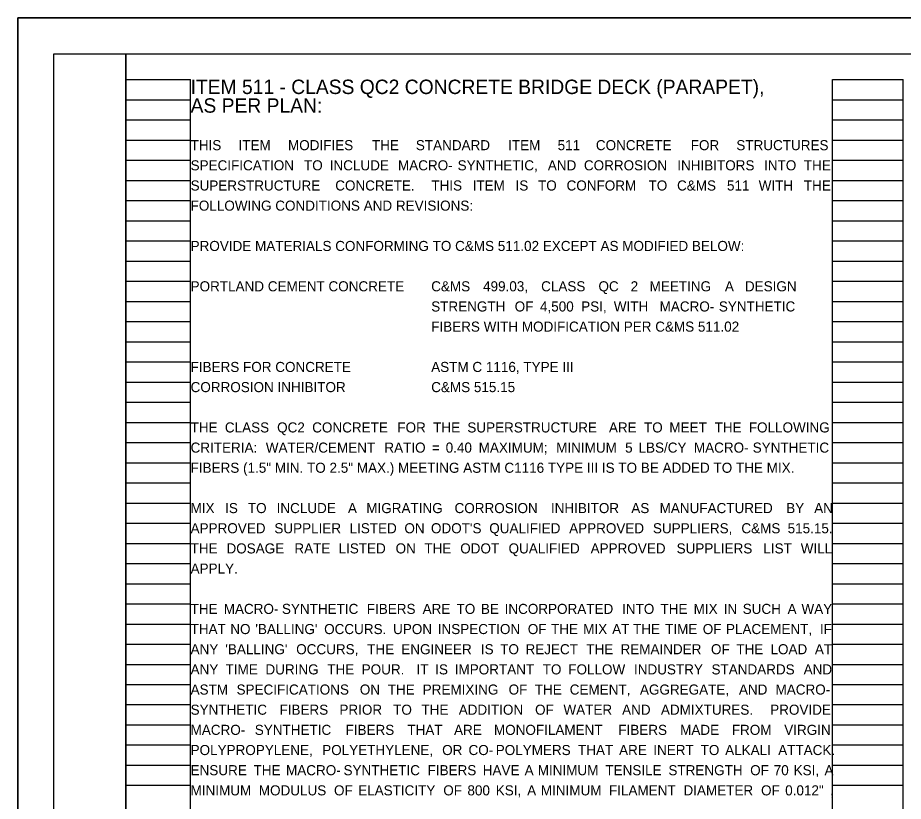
# Model space of a CAD drawing. Extents: x 0 to 34, y 0 to 22.
# Drawn here: x 0 to 12.29, y 11.12 to 22 of the extents above; entities that cross this region are included whole.
import ezdxf

# ---------------------------------------------------------------- set-up
doc = ezdxf.new("R2010")
doc.units = 0
for name, color, linetype in [('BR_P_Gen_Text', 7, 'Continuous'), ('SC_Scratch1', 7, 'Continuous'), ('SH_Border', 7, 'Continuous'), ('SH_Cut_Line', 7, 'Continuous'), ('SH_Text', 7, 'Continuous'), ('SN_P_Cantilever_Overhead', 7, 'Continuous')]:
    doc.layers.add(name, color=color, linetype=linetype)

msp = doc.modelspace()

# ---------------------------------------------------------------- linework, layer by layer
at = {"layer": 'SC_Scratch1'}
for p, q in [((1.5, 0.98), (1.5, 21.14)), ((1.5, 21.14), (2.4, 21.14)), ((2.4, 0.98), (2.4, 21.14)), ((11.313, 0.98), (11.313, 21.14)), ((11.313, 21.14), (12.293, 21.14)), ((12.293, 0.98), (12.293, 21.14)), ((1.5, 20.86), (2.4, 20.86)), ((11.313, 20.86), (12.293, 20.86)), ((1.5, 20.58), (2.4, 20.58)), ((11.313, 20.58), (12.293, 20.58)), ((1.5, 20.3), (2.4, 20.3)), ((11.313, 20.3), (12.293, 20.3)), ((1.5, 20.02), (2.4, 20.02)), ((11.313, 20.02), (12.293, 20.02)), ((1.5, 19.74), (2.4, 19.74)), ((11.313, 19.74), (12.293, 19.74)), ((1.5, 19.46), (2.4, 19.46)), ((11.313, 19.46), (12.293, 19.46)), ((1.5, 19.18), (2.4, 19.18)), ((11.313, 19.18), (12.293, 19.18)), ((1.5, 18.9), (2.4, 18.9)), ((11.313, 18.9), (12.293, 18.9)), ((1.5, 18.62), (2.4, 18.62)), ((11.313, 18.62), (12.293, 18.62)), ((1.5, 18.34), (2.4, 18.34)), ((11.313, 18.34), (12.293, 18.34)), ((1.5, 18.06), (2.4, 18.06)), ((11.313, 18.06), (12.293, 18.06)), ((1.5, 17.78), (2.4, 17.78)), ((11.313, 17.78), (12.293, 17.78)), ((1.5, 17.5), (2.4, 17.5)), ((11.313, 17.5), (12.293, 17.5)), ((1.5, 17.22), (2.4, 17.22)), ((11.313, 17.22), (12.293, 17.22)), ((1.5, 16.94), (2.4, 16.94)), ((11.313, 16.94), (12.293, 16.94)), ((1.5, 16.66), (2.4, 16.66)), ((11.313, 16.66), (12.293, 16.66)), ((1.5, 16.38), (2.4, 16.38)), ((11.313, 16.38), (12.293, 16.38)), ((1.5, 16.1), (2.4, 16.1)), ((11.313, 16.1), (12.293, 16.1)), ((1.5, 15.82), (2.4, 15.82)), ((11.313, 15.82), (12.293, 15.82)), ((1.5, 15.54), (2.4, 15.54)), ((11.313, 15.54), (12.293, 15.54)), ((1.5, 15.26), (2.4, 15.26)), ((11.313, 15.26), (12.293, 15.26)), ((1.5, 14.98), (2.4, 14.98)), ((11.313, 14.98), (12.293, 14.98)), ((1.5, 14.7), (2.4, 14.7)), ((11.313, 14.7), (12.293, 14.7)), ((1.5, 14.42), (2.4, 14.42)), ((11.313, 14.42), (12.293, 14.42)), ((1.5, 14.14), (2.4, 14.14)), ((11.313, 14.14), (12.293, 14.14)), ((1.5, 13.86), (2.4, 13.86)), ((11.313, 13.86), (12.293, 13.86)), ((1.5, 13.58), (2.4, 13.58)), ((11.313, 13.58), (12.293, 13.58)), ((1.5, 13.3), (2.4, 13.3)), ((11.313, 13.3), (12.293, 13.3)), ((1.5, 13.02), (2.4, 13.02)), ((11.313, 13.02), (12.293, 13.02)), ((1.5, 12.74), (2.4, 12.74)), ((11.313, 12.74), (12.293, 12.74)), ((1.5, 12.46), (2.4, 12.46)), ((11.313, 12.46), (12.293, 12.46)), ((1.5, 12.18), (2.4, 12.18)), ((11.313, 12.18), (12.293, 12.18)), ((1.5, 11.9), (2.4, 11.9)), ((11.313, 11.9), (12.293, 11.9)), ((1.5, 11.62), (2.4, 11.62)), ((11.313, 11.62), (12.293, 11.62)), ((1.5, 11.34), (2.4, 11.34)), ((11.313, 11.34), (12.293, 11.34))]:
    msp.add_line(p, q, dxfattribs=at)
msp.add_lwpolyline([(0, 22), (34, 22), (34, 0), (0, 0)], close=True, dxfattribs=at)
at = {"layer": 'SH_Border'}
for points in [[(0.5, 21.5), (1.5, 21.5), (1.5, 0.5), (0.5, 0.5)], [(1.5, 21.5), (33.5, 21.5), (33.5, 0.5), (1.5, 0.5)]]:
    msp.add_lwpolyline(points, close=True, dxfattribs=at)
at = {"layer": 'SH_Cut_Line'}
msp.add_lwpolyline([(0, 0), (34, 0), (34, 22), (0, 22)], close=True, dxfattribs=at)

# ---------------------------------------------------------------- texts
at = {"layer": 'BR_P_Gen_Text'}
for s, p in [('ITEM 511 - CLASS QC2 CONCRETE BRIDGE DECK (PARAPET), ', (2.4, 20.94)), ('AS PER PLAN:', (2.4, 20.681))]:
    msp.add_text(s, height=0.2, dxfattribs=at).set_placement(p)
at = {"layer": 'SH_Text'}
for s, p in [('THIS ', (2.4, 20.16)), ('ITEM ', (3.065, 20.16)), ('MODIFIES ', (3.752, 20.16)), ('THE ', (4.917, 20.16)), ('STANDARD ', (5.527, 20.16)), ('ITEM ', (6.808, 20.16)), ('511 ', (7.495, 20.16)), ('CONCRETE ', (8.026, 20.16)), ('FOR ', (9.343, 20.16)), ('STRUCTURES ', (9.976, 20.16)), ('SPECIFICATION ', (2.4, 19.88)), ('TO ', (3.974, 19.88)), ('INCLUDE ', (4.331, 19.88)), ('MACRO-', (5.279, 19.88)), ('SYNTHETIC, ', (6.107, 19.88)), ('AND ', (7.359, 19.88)), ('CORROSION ', (7.86, 19.88)), ('INHIBITORS ', (9.156, 19.88)), ('INTO ', (10.361, 19.88)), ('THE ', (10.913, 19.88)), ('SUPERSTRUCTURE ', (2.4, 19.6)), ('CONCRETE.  ', (4.408, 19.6)), ('THIS ', (5.742, 19.6)), ('ITEM ', (6.316, 19.6)), ('IS ', (6.911, 19.6)), ('TO ', (7.223, 19.6)), ('CONFORM ', (7.619, 19.6)), ('TO ', (8.757, 19.6)), ('C&MS ', (9.153, 19.6)), ('511 ', (9.846, 19.6)), ('WITH ', (10.286, 19.6)), ('THE ', (10.913, 19.6)), ('FOLLOWING CONDITIONS AND REVISIONS:', (2.4, 19.32)), ('PROVIDE MATERIALS CONFORMING TO C&MS 511.02 EXCEPT AS MODIFIED BELOW:', (2.4, 18.76)), ('PORTLAND CEMENT CONCRETE', (2.4, 18.2)), ('FIBERS FOR CONCRETE', (2.4, 17.08)), ('CORROSION INHIBITOR', (2.4, 16.8)), ('THE ', (2.4, 16.24)), ('CLASS ', (2.876, 16.24)), ('QC2 ', (3.601, 16.24)), ('CONCRETE ', (4.088, 16.24)), ('FOR ', (5.27, 16.24)), ('THE ', (5.767, 16.24)), ('SUPERSTRUCTURE ', (6.242, 16.24)), ('ARE ', (8.207, 16.24)), ('TO ', (8.694, 16.24)), ('MEET ', (9.046, 16.24)), ('THE ', (9.674, 16.24)), ('FOLLOWING ', (10.149, 16.24)), ('WATER/CEMENT ', (3.444, 15.96)), ('LBS/CY ', (8.618, 15.96)), ('CRITERIA: ', (2.4, 15.96)), ('RATIO ', (5.09, 15.96)), ('= ', (5.75, 15.96)), ('0.40 ', (5.941, 15.96)), ('MAXIMUM; ', (6.399, 15.96)), ('MINIMUM ', (7.475, 15.96)), ('5 ', (8.432, 15.96)), ('MACRO-', (9.387, 15.96)), ('SYNTHETIC ', (10.203, 15.96)), ('FIBERS (1.5" MIN. TO 2.5" MAX.) MEETING ASTM C1116 TYPE III IS TO BE ADDED TO THE MIX.', (2.4, 15.68)), ('MIX ', (2.4, 15.12)), ('IS ', (2.879, 15.12)), ('TO ', (3.195, 15.12)), ('INCLUDE ', (3.594, 15.12)), ('A ', (4.584, 15.12)), ('MIGRATING ', (4.839, 15.12)), ('CORROSION ', (6.064, 15.12)), ('INHIBITOR ', (7.402, 15.12)), ('AS ', (8.518, 15.12)), ('MANUFACTURED ', (8.911, 15.12)), ('BY ', (10.668, 15.12)), ('AN ', (11.057, 15.12)), ('APPROVED ', (2.4, 14.84)), ('SUPPLIER ', (3.563, 14.84)), ('LISTED ', (4.607, 14.84)), ('ON ', (5.368, 14.84)), ("ODOT'S ", (5.737, 14.84)), ('QUALIFIED ', (6.546, 14.84)), ('APPROVED ', (7.655, 14.84)), ('SUPPLIERS, ', (8.818, 14.84)), ('C&MS ', (10.046, 14.84)), ('515.15.    ', (10.688, 14.84)), ('THE ', (2.4, 14.56)), ('DOSAGE ', (2.898, 14.56)), ('RATE ', (3.841, 14.56)), ('LISTED ', (4.454, 14.56)), ('ON ', (5.246, 14.56)), ('THE ', (5.645, 14.56)), ('ODOT ', (6.143, 14.56)), ('QUALIFIED ', (6.814, 14.56)), ('APPROVED ', (7.953, 14.56)), ('SUPPLIERS ', (9.147, 14.56)), ('LIST ', (10.351, 14.56)), ('WILL ', (10.87, 14.56)), ('APPLY.  ', (2.4, 14.28)), ('THE ', (2.4, 13.72)), ('MACRO-', (2.86, 13.72)), ('SYNTHETIC ', (3.668, 13.72)), ('FIBERS ', (4.846, 13.72)), ('ARE ', (5.621, 13.72)), ('TO ', (6.092, 13.72)), ('BE ', (6.43, 13.72)), ('INCORPORATED ', (6.759, 13.72)), ('INTO ', (8.39, 13.72)), ('THE ', (8.923, 13.72)), ('MIX ', (9.383, 13.72)), ('IN ', (9.8, 13.72)), ('SUCH ', (10.064, 13.72)), ('A ', (10.687, 13.72)), ('WAY ', (10.88, 13.72)), ('THAT ', (2.4, 13.44)), ('NO ', (2.951, 13.44)), ("'BALLING' ", (3.299, 13.44)), ('OCCURS. ', (4.254, 13.44)), ('UPON ', (5.211, 13.44)), ('INSPECTION ', (5.831, 13.44)), ('OF ', (7.081, 13.44)), ('THE ', (7.404, 13.44)), ('MIX ', (7.85, 13.44)), ('AT ', (8.252, 13.44)), ('THE ', (8.542, 13.44)), ('TIME ', (8.988, 13.44)), ('OF ', (9.51, 13.44)), ('PLACEMENT, ', (9.832, 13.44)), ('IF ', (11.137, 13.44)), ('ANY ', (2.4, 13.16)), ("'BALLING' ", (2.882, 13.16)), ('OCCURS, ', (3.866, 13.16)), ('THE ', (4.851, 13.16)), ('ENGINEER ', (5.325, 13.16)), ('IS ', (6.43, 13.16)), ('TO ', (6.698, 13.16)), ('REJECT ', (7.049, 13.16)), ('THE ', (7.893, 13.16)), ('REMAINDER ', (8.368, 13.16)), ('OF ', (9.624, 13.16)), ('THE ', (9.976, 13.16)), ('LOAD ', (10.45, 13.16)), ('AT ', (11.066, 13.16)), ('ANY ', (2.4, 12.88)), ('TIME ', (2.885, 12.88)), ('DURING ', (3.439, 12.88)), ('THE ', (4.297, 12.88)), ('POUR.  ', (4.775, 12.88)), ('IT ', (5.536, 12.88)), ('IS ', (5.796, 12.88)), ('IMPORTANT ', (6.067, 12.88)), ('TO ', (7.288, 12.88)), ('FOLLOW ', (7.643, 12.88)), ('INDUSTRY ', (8.555, 12.88)), ('STANDARDS ', (9.631, 12.88)), ('AND ', (10.91, 12.88)), ('ASTM ', (2.4, 12.6)), ('SPECIFICATIONS ', (3.038, 12.6)), ('ON ', (4.749, 12.6)), ('THE ', (5.137, 12.6)), ('PREMIXING ', (5.622, 12.6)), ('OF ', (6.815, 12.6)), ('THE ', (7.178, 12.6)), ('CEMENT, ', (7.663, 12.6)), ('AGGREGATE, ', (8.638, 12.6)), ('AND ', (10.012, 12.6)), ('MACRO-', (10.52, 12.6)), ('SYNTHETIC ', (2.4, 12.32)), ('FIBERS ', (3.634, 12.32)), ('PRIOR ', (4.466, 12.32)), ('TO ', (5.212, 12.32)), ('THE ', (5.605, 12.32)), ('ADDITION ', (6.122, 12.32)), ('OF ', (7.182, 12.32)), ('WATER ', (7.576, 12.32)), ('AND ', (8.39, 12.32)), ('ADMIXTURES.  ', (8.929, 12.32)), ('PROVIDE ', (10.446, 12.32)), ('MACRO-', (2.4, 12.04)), ('SYNTHETIC ', (3.291, 12.04)), ('FIBERS ', (4.551, 12.04)), ('THAT ', (5.409, 12.04)), ('ARE ', (6.057, 12.04)), ('MONOFILAMENT ', (6.611, 12.04)), ('FIBERS ', (8.338, 12.04)), ('MADE ', (9.196, 12.04)), ('FROM ', (9.913, 12.04)), ('VIRGIN ', (10.641, 12.04)), ('POLYPROPYLENE, ', (2.4, 11.76)), ('POLYETHYLENE, ', (4.227, 11.76)), ('OR ', (5.892, 11.76)), ('CO-', (6.258, 11.76)), ('POLYMERS ', (6.636, 11.76)), ('THAT ', (7.778, 11.76)), ('ARE ', (8.348, 11.76)), ('INERT ', (8.823, 11.76)), ('TO ', (9.48, 11.76)), ('ALKALI ', (9.821, 11.76)), ('ATTACK.  ', (10.557, 11.76)), ('ENSURE ', (2.4, 11.48)), ('THE ', (3.274, 11.48)), ('MACRO-', (3.725, 11.48)), ('SYNTHETIC ', (4.523, 11.48)), ('FIBERS ', (5.69, 11.48)), ('HAVE ', (6.456, 11.48)), ('A ', (7.037, 11.48)), ('MINIMUM ', (7.219, 11.48)), ('TENSILE ', (8.158, 11.48)), ('STRENGTH ', (9.033, 11.48)), ('OF ', (10.168, 11.48)), ('70 ', (10.495, 11.48)), ('KSI, ', (10.771, 11.48)), ('A ', (11.2, 11.48)), ('MINIMUM ', (2.4, 11.2)), ('MODULUS ', (3.347, 11.2)), ('OF ', (4.391, 11.2)), ('ELASTICITY ', (4.726, 11.2)), ('OF ', (5.908, 11.2)), ('800 ', (6.243, 11.2)), ('KSI, ', (6.636, 11.2)), ('A ', (7.072, 11.2)), ('MINIMUM ', (7.262, 11.2)), ('FILAMENT ', (8.208, 11.2)), ('DIAMETER ', (9.242, 11.2)), ('OF ', (10.319, 11.2)), ('0.012" ', (10.654, 11.2)), (', ', (11.279, 11.2))]:
    msp.add_text(s, height=0.14, dxfattribs=at).set_placement(p)
at = {"layer": 'SN_P_Cantilever_Overhead'}
for s, p in [('C&MS ', (5.74, 18.2)), ('499.03, ', (6.46, 18.2)), ('CLASS ', (7.266, 18.2)), ('QC ', (8.062, 18.2)), ('2 ', (8.509, 18.2)), ('MEETING ', (8.772, 18.2)), ('A ', (9.817, 18.2)), ('DESIGN ', (10.095, 18.2)), ('STRENGTH ', (5.74, 17.92)), ('OF ', (6.899, 17.92)), ('4,500 ', (7.25, 17.92)), ('PSI, ', (7.822, 17.92)), ('WITH  ', (8.275, 17.92)), ('MACRO-', (8.911, 17.92)), ('SYNTHETIC ', (9.733, 17.92)), ('FIBERS WITH MODIFICATION PER C&MS 511.02', (5.74, 17.64)), ('ASTM C 1116, TYPE III', (5.74, 17.08)), ('C&MS 515.15', (5.74, 16.8))]:
    msp.add_text(s, height=0.14, dxfattribs=at).set_placement(p)

doc.saveas('drawing.dxf')
